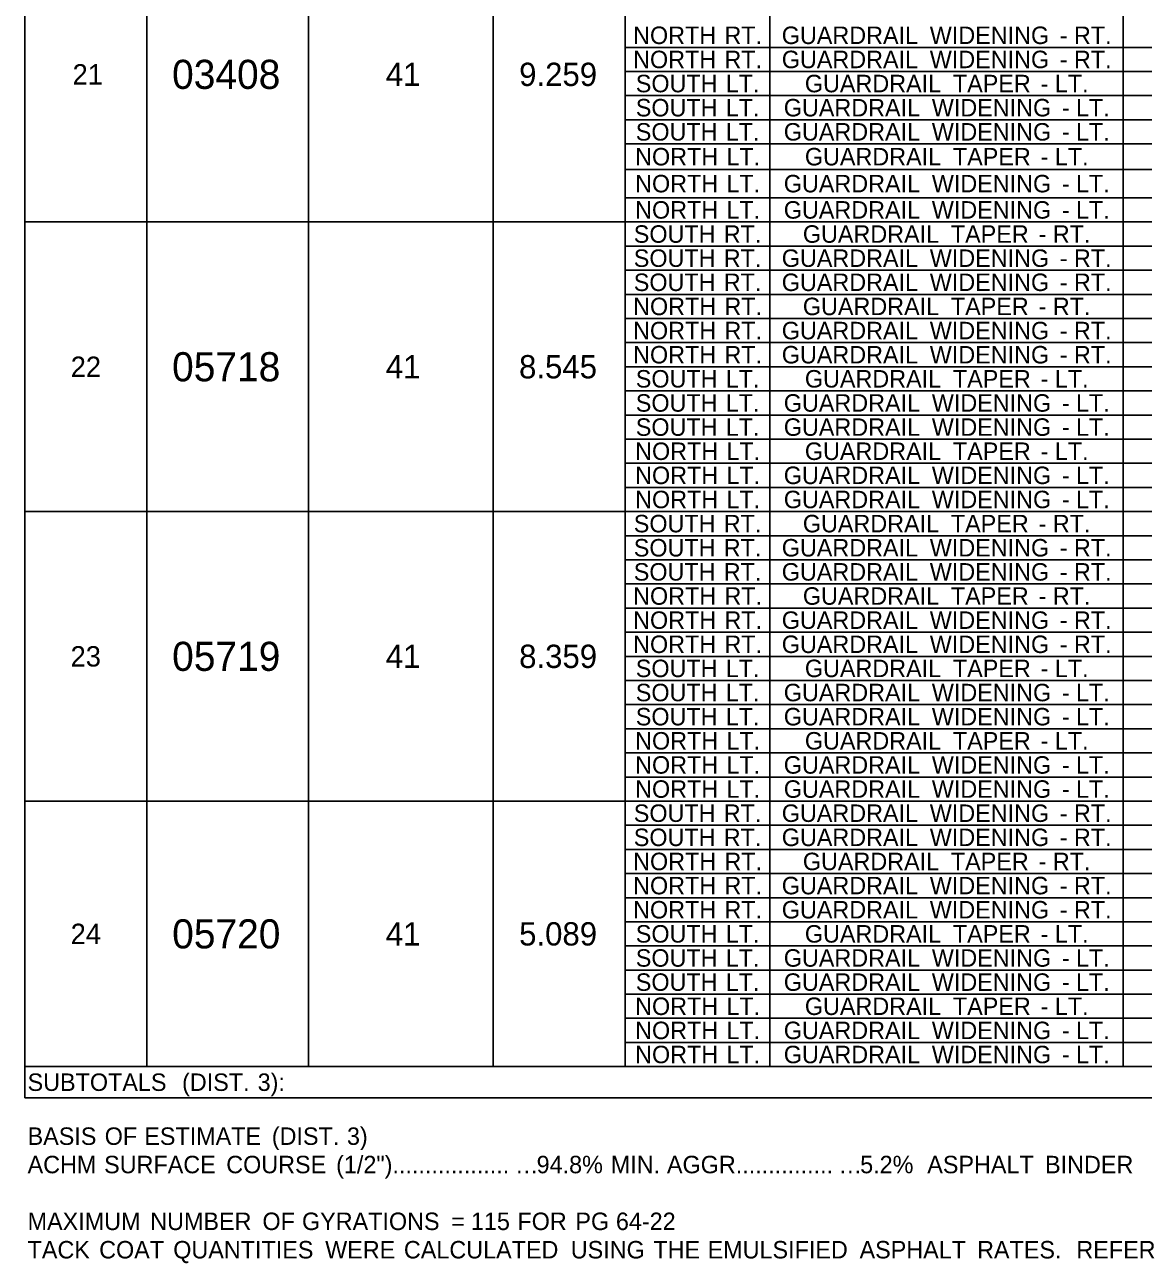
# Model space of a CAD drawing. Extents: x 544250 to 1930787, y -1948365 to 596640.
# Drawn here: x 557554.3 to 557938.5, y -1946895.1 to -1946469.8 of the extents above; entities that cross this region are included whole.
import ezdxf

# ---------------------------------------------------------------- set-up
doc = ezdxf.new("R2010")
doc.units = 0
doc.layers.add('Default', color=7, linetype='Continuous')

msp = doc.modelspace()

# ---------------------------------------------------------------- linework, layer by layer
at = {"layer": 'Default'}
for p, q in [((557554.29, -1946838.27), (557554.29, -1946062.17)), ((557596.21, -1946827.55), (557596.21, -1946062.17)), ((557651.79, -1946827.55), (557651.79, -1946062.17)), ((557715.16, -1946827.55), (557715.16, -1946062.17)), ((557760.5, -1946827.55), (557760.5, -1946062.17)), ((557810.22, -1946827.55), (557810.22, -1946062.17)), ((557931.61, -1946827.55), (557931.61, -1946062.17)), ((557760.5, -1946477.52), (558237.27, -1946477.52)), ((557760.5, -1946485.81), (558237.27, -1946485.81)), ((557760.5, -1946494.1), (558237.27, -1946494.1)), ((557760.5, -1946502.39), (558237.27, -1946502.39)), ((557760.5, -1946510.67), (558237.27, -1946510.67)), ((557760.5, -1946519.45), (558237.27, -1946519.45)), ((557760.5, -1946529.2), (558237.27, -1946529.2)), ((557554.29, -1946537.49), (558237.27, -1946537.49)), ((557760.5, -1946545.77), (558237.27, -1946545.77)), ((557760.5, -1946554.06), (558237.27, -1946554.06)), ((557760.5, -1946562.35), (558237.27, -1946562.35)), ((557760.5, -1946570.64), (558237.27, -1946570.64)), ((557760.5, -1946578.92), (558237.27, -1946578.92)), ((557760.5, -1946587.21), (558237.27, -1946587.21)), ((557760.5, -1946595.5), (558237.27, -1946595.5)), ((557760.5, -1946603.79), (558237.27, -1946603.79)), ((557760.5, -1946612.07), (558237.27, -1946612.07)), ((557760.5, -1946620.36), (558237.27, -1946620.36)), ((557760.5, -1946628.65), (558237.27, -1946628.65)), ((557554.29, -1946636.94), (558237.27, -1946636.94)), ((557760.5, -1946645.22), (558237.27, -1946645.22)), ((557760.5, -1946653.51), (558237.27, -1946653.51)), ((557760.5, -1946661.8), (558237.27, -1946661.8)), ((557760.5, -1946670.09), (558237.27, -1946670.09)), ((557760.5, -1946678.37), (558237.27, -1946678.37)), ((557760.5, -1946686.66), (558237.27, -1946686.66)), ((557760.5, -1946694.95), (558237.27, -1946694.95)), ((557760.5, -1946703.24), (558237.27, -1946703.24)), ((557760.5, -1946711.52), (558237.27, -1946711.52)), ((557760.5, -1946719.81), (558237.27, -1946719.81)), ((557760.5, -1946728.1), (558237.27, -1946728.1)), ((557554.29, -1946736.39), (558237.27, -1946736.39)), ((557760.5, -1946736.39), (558237.27, -1946736.39)), ((557760.5, -1946744.67), (558237.27, -1946744.67)), ((557760.5, -1946752.96), (558237.27, -1946752.96)), ((557760.5, -1946761.25), (558237.27, -1946761.25)), ((557760.5, -1946769.54), (558237.27, -1946769.54)), ((557760.5, -1946777.82), (558237.27, -1946777.82)), ((557760.5, -1946786.11), (558237.27, -1946786.11)), ((557760.5, -1946794.4), (558237.27, -1946794.4)), ((557760.5, -1946802.69), (558237.27, -1946802.69)), ((557760.5, -1946810.97), (558237.27, -1946810.97)), ((557760.5, -1946819.26), (558237.27, -1946819.26)), ((557554.29, -1946827.55), (558237.27, -1946827.55)), ((557554.29, -1946838.27), (558237.27, -1946838.27))]:
    msp.add_line(p, q, dxfattribs=at)

# ---------------------------------------------------------------- texts
for s, height, p in [('NORTH', 6, (557763.25, -1946476.38)), (' RT.', 6, (557792.38, -1946476.38)), ('GUARDRAIL', 6, (557814.31, -1946476.38)), (' WIDENING', 6, (557862.92, -1946476.38)), (' RT.', 6, (557912.43, -1946476.38)), (' -', 6, (557907.57, -1946476.38)), ('NORTH', 6, (557763.25, -1946484.67)), (' RT.', 6, (557792.38, -1946484.67)), ('GUARDRAIL', 6, (557814.31, -1946484.67)), (' WIDENING', 6, (557862.92, -1946484.67)), (' RT.', 6, (557912.43, -1946484.67)), ('21', 7, (557570.71, -1946490.29)), ('03408', 10, (557604.89, -1946491.79)), ('41', 8, (557678.29, -1946490.79)), ('9.259', 8, (557724.1, -1946490.79)), (' -', 6, (557907.57, -1946484.67)), ('SOUTH', 6, (557764.17, -1946492.95)), (' LT.', 6, (557792.84, -1946492.95)), ('GUARDRAIL', 6, (557822.24, -1946492.95)), (' TAPER', 6, (557870.86, -1946492.95)), (' LT.', 6, (557905.89, -1946492.95)), (' -', 6, (557901.03, -1946492.95)), ('SOUTH', 6, (557764.17, -1946501.24)), (' LT.', 6, (557792.84, -1946501.24)), ('GUARDRAIL', 6, (557815, -1946501.24)), (' WIDENING', 6, (557863.62, -1946501.24)), (' LT.', 6, (557913.13, -1946501.24)), (' -', 6, (557908.27, -1946501.24)), ('SOUTH', 6, (557764.17, -1946509.53)), (' LT.', 6, (557792.84, -1946509.53)), ('GUARDRAIL', 6, (557815, -1946509.53)), (' WIDENING', 6, (557863.62, -1946509.53)), (' LT.', 6, (557913.13, -1946509.53)), (' -', 6, (557908.27, -1946509.53)), ('NORTH', 6, (557763.94, -1946518.06)), (' LT.', 6, (557793.07, -1946518.06)), ('GUARDRAIL', 6, (557822.24, -1946518.06)), (' TAPER', 6, (557870.86, -1946518.06)), (' LT.', 6, (557905.89, -1946518.06)), (' -', 6, (557901.03, -1946518.06)), ('NORTH', 6, (557763.94, -1946527.32)), (' LT.', 6, (557793.07, -1946527.32)), ('GUARDRAIL', 6, (557815, -1946527.32)), (' WIDENING', 6, (557863.62, -1946527.32)), (' LT.', 6, (557913.13, -1946527.32)), (' -', 6, (557908.27, -1946527.32)), ('NORTH', 6, (557763.94, -1946536.34)), (' LT.', 6, (557793.07, -1946536.34)), ('GUARDRAIL', 6, (557815, -1946536.34)), (' WIDENING', 6, (557863.62, -1946536.34)), (' LT.', 6, (557913.13, -1946536.34)), (' -', 6, (557908.27, -1946536.34)), ('SOUTH', 6, (557763.48, -1946544.63)), (' RT.', 6, (557792.15, -1946544.63)), ('GUARDRAIL', 6, (557821.55, -1946544.63)), (' TAPER', 6, (557870.16, -1946544.63)), (' RT.', 6, (557905.19, -1946544.63)), (' -', 6, (557900.33, -1946544.63)), ('SOUTH', 6, (557763.48, -1946552.92)), (' RT.', 6, (557792.15, -1946552.92)), ('GUARDRAIL', 6, (557814.31, -1946552.92)), (' WIDENING', 6, (557862.92, -1946552.92)), (' RT.', 6, (557912.43, -1946552.92)), (' -', 6, (557907.57, -1946552.92)), ('SOUTH', 6, (557763.48, -1946561.2)), (' RT.', 6, (557792.15, -1946561.2)), ('GUARDRAIL', 6, (557814.31, -1946561.2)), (' WIDENING', 6, (557862.92, -1946561.2)), (' RT.', 6, (557912.43, -1946561.2)), (' -', 6, (557907.57, -1946561.2)), ('NORTH', 6, (557763.25, -1946569.49)), (' RT.', 6, (557792.38, -1946569.49)), ('GUARDRAIL', 6, (557821.55, -1946569.49)), (' TAPER', 6, (557870.16, -1946569.49)), (' RT.', 6, (557905.19, -1946569.49)), (' -', 6, (557900.33, -1946569.49)), ('NORTH', 6, (557763.25, -1946577.78)), (' RT.', 6, (557792.38, -1946577.78)), ('GUARDRAIL', 6, (557814.31, -1946577.78)), (' WIDENING', 6, (557862.92, -1946577.78)), (' RT.', 6, (557912.43, -1946577.78)), (' -', 6, (557907.57, -1946577.78)), ('05718', 10, (557604.89, -1946592.21)), ('NORTH', 6, (557763.25, -1946586.07)), (' RT.', 6, (557792.38, -1946586.07)), ('GUARDRAIL', 6, (557814.31, -1946586.07)), (' WIDENING', 6, (557862.92, -1946586.07)), (' RT.', 6, (557912.43, -1946586.07)), ('22', 7, (557570.07, -1946590.71)), ('41', 8, (557678.29, -1946591.21)), ('8.545', 8, (557724.07, -1946591.21)), (' -', 6, (557907.57, -1946586.07)), ('SOUTH', 6, (557764.17, -1946594.35)), (' LT.', 6, (557792.84, -1946594.35)), ('GUARDRAIL', 6, (557822.24, -1946594.35)), (' TAPER', 6, (557870.86, -1946594.35)), (' LT.', 6, (557905.89, -1946594.35)), (' -', 6, (557901.03, -1946594.35)), ('SOUTH', 6, (557764.17, -1946602.64)), (' LT.', 6, (557792.84, -1946602.64)), ('GUARDRAIL', 6, (557815, -1946602.64)), (' WIDENING', 6, (557863.62, -1946602.64)), (' LT.', 6, (557913.13, -1946602.64)), (' -', 6, (557908.27, -1946602.64)), ('SOUTH', 6, (557764.17, -1946610.93)), (' LT.', 6, (557792.84, -1946610.93)), ('GUARDRAIL', 6, (557815, -1946610.93)), (' WIDENING', 6, (557863.62, -1946610.93)), (' -', 6, (557908.27, -1946610.93)), (' LT.', 6, (557913.13, -1946610.93)), ('NORTH', 6, (557763.94, -1946619.22)), (' LT.', 6, (557793.07, -1946619.22)), ('GUARDRAIL', 6, (557822.24, -1946619.22)), (' TAPER', 6, (557870.86, -1946619.22)), (' -', 6, (557901.03, -1946619.22)), (' LT.', 6, (557905.89, -1946619.22)), ('NORTH', 6, (557763.94, -1946627.5)), (' LT.', 6, (557793.07, -1946627.5)), ('GUARDRAIL', 6, (557815, -1946627.5)), (' WIDENING', 6, (557863.62, -1946627.5)), (' -', 6, (557908.27, -1946627.5)), (' LT.', 6, (557913.13, -1946627.5)), ('NORTH', 6, (557763.94, -1946635.79)), (' LT.', 6, (557793.07, -1946635.79)), ('GUARDRAIL', 6, (557815, -1946635.79)), (' WIDENING', 6, (557863.62, -1946635.79)), (' -', 6, (557908.27, -1946635.79)), (' LT.', 6, (557913.13, -1946635.79)), ('SOUTH', 6, (557763.48, -1946644.08)), ('GUARDRAIL', 6, (557821.55, -1946644.08)), (' RT.', 6, (557792.15, -1946644.08)), (' TAPER', 6, (557870.16, -1946644.08)), (' -', 6, (557900.33, -1946644.08)), (' RT.', 6, (557905.19, -1946644.08)), ('SOUTH', 6, (557763.48, -1946652.37)), (' RT.', 6, (557792.15, -1946652.37)), ('GUARDRAIL', 6, (557814.31, -1946652.37)), (' WIDENING', 6, (557862.92, -1946652.37)), (' RT.', 6, (557912.43, -1946652.37)), (' -', 6, (557907.57, -1946652.37)), ('SOUTH', 6, (557763.48, -1946660.65)), (' RT.', 6, (557792.15, -1946660.65)), ('GUARDRAIL', 6, (557814.31, -1946660.65)), (' WIDENING', 6, (557862.92, -1946660.65)), (' RT.', 6, (557912.43, -1946660.65)), (' -', 6, (557907.57, -1946660.65)), ('NORTH', 6, (557763.25, -1946668.94)), (' RT.', 6, (557792.38, -1946668.94)), ('GUARDRAIL', 6, (557821.55, -1946668.94)), (' TAPER', 6, (557870.16, -1946668.94)), (' RT.', 6, (557905.19, -1946668.94)), (' -', 6, (557900.33, -1946668.94)), ('NORTH', 6, (557763.25, -1946677.23)), (' RT.', 6, (557792.38, -1946677.23)), ('GUARDRAIL', 6, (557814.31, -1946677.23)), (' WIDENING', 6, (557862.92, -1946677.23)), (' RT.', 6, (557912.43, -1946677.23)), (' -', 6, (557907.57, -1946677.23)), ('NORTH', 6, (557763.25, -1946685.52)), (' RT.', 6, (557792.38, -1946685.52)), ('GUARDRAIL', 6, (557814.31, -1946685.52)), (' WIDENING', 6, (557862.92, -1946685.52)), (' RT.', 6, (557912.43, -1946685.52)), ('23', 7, (557570.03, -1946690.16)), ('05719', 10, (557604.91, -1946691.66)), ('41', 8, (557678.29, -1946690.66)), ('8.359', 8, (557724.1, -1946690.66)), (' -', 6, (557907.57, -1946685.52)), ('SOUTH', 6, (557764.17, -1946693.8)), (' LT.', 6, (557792.84, -1946693.8)), ('GUARDRAIL', 6, (557822.24, -1946693.8)), (' TAPER', 6, (557870.86, -1946693.8)), (' LT.', 6, (557905.89, -1946693.8)), (' -', 6, (557901.03, -1946693.8)), ('SOUTH', 6, (557764.17, -1946702.09)), (' LT.', 6, (557792.84, -1946702.09)), ('GUARDRAIL', 6, (557815, -1946702.09)), (' WIDENING', 6, (557863.62, -1946702.09)), (' LT.', 6, (557913.13, -1946702.09)), (' -', 6, (557908.27, -1946702.09)), ('SOUTH', 6, (557764.17, -1946710.38)), (' LT.', 6, (557792.84, -1946710.38)), ('GUARDRAIL', 6, (557815, -1946710.38)), (' WIDENING', 6, (557863.62, -1946710.38)), (' LT.', 6, (557913.13, -1946710.38)), (' -', 6, (557908.27, -1946710.38)), ('NORTH', 6, (557763.94, -1946718.67)), (' LT.', 6, (557793.07, -1946718.67)), ('GUARDRAIL', 6, (557822.24, -1946718.67)), (' TAPER', 6, (557870.86, -1946718.67)), (' LT.', 6, (557905.89, -1946718.67)), (' -', 6, (557901.03, -1946718.67)), ('NORTH', 6, (557763.94, -1946726.95)), (' LT.', 6, (557793.07, -1946726.95)), ('GUARDRAIL', 6, (557815, -1946726.95)), (' WIDENING', 6, (557863.62, -1946726.95)), (' LT.', 6, (557913.13, -1946726.95)), (' -', 6, (557908.27, -1946726.95)), ('NORTH', 6, (557763.94, -1946735.24)), (' LT.', 6, (557793.07, -1946735.24)), ('GUARDRAIL', 6, (557815, -1946735.24)), (' WIDENING', 6, (557863.62, -1946735.24)), (' LT.', 6, (557913.13, -1946735.24)), (' -', 6, (557908.27, -1946735.24)), ('SOUTH', 6, (557763.48, -1946743.53)), (' RT.', 6, (557792.15, -1946743.53)), ('GUARDRAIL', 6, (557814.31, -1946743.53)), (' WIDENING', 6, (557862.92, -1946743.53)), (' RT.', 6, (557912.43, -1946743.53)), (' -', 6, (557907.57, -1946743.53)), ('SOUTH', 6, (557763.48, -1946751.82)), (' RT.', 6, (557792.15, -1946751.82)), ('GUARDRAIL', 6, (557814.31, -1946751.82)), (' WIDENING', 6, (557862.92, -1946751.82)), (' RT.', 6, (557912.43, -1946751.82)), (' -', 6, (557907.57, -1946751.82)), ('NORTH', 6, (557763.25, -1946760.1)), (' RT.', 6, (557792.38, -1946760.1)), ('GUARDRAIL', 6, (557821.55, -1946760.1)), (' TAPER', 6, (557870.16, -1946760.1)), (' RT.', 6, (557905.19, -1946760.1)), (' -', 6, (557900.33, -1946760.1)), ('NORTH', 6, (557763.25, -1946768.39)), (' RT.', 6, (557792.38, -1946768.39)), ('GUARDRAIL', 6, (557814.31, -1946768.39)), (' WIDENING', 6, (557862.92, -1946768.39)), (' RT.', 6, (557912.43, -1946768.39)), (' -', 6, (557907.57, -1946768.39)), ('NORTH', 6, (557763.25, -1946776.68)), (' RT.', 6, (557792.38, -1946776.68)), ('GUARDRAIL', 6, (557814.31, -1946776.68)), (' WIDENING', 6, (557862.92, -1946776.68)), (' -', 6, (557907.57, -1946776.68)), (' RT.', 6, (557912.43, -1946776.68)), ('24', 7, (557570.05, -1946785.47)), ('05720', 10, (557604.92, -1946786.97)), ('41', 8, (557678.29, -1946785.97)), ('5.089', 8, (557724.1, -1946785.97)), ('SOUTH', 6, (557764.17, -1946784.97)), (' LT.', 6, (557792.84, -1946784.97)), ('GUARDRAIL', 6, (557822.24, -1946784.97)), (' TAPER', 6, (557870.86, -1946784.97)), (' -', 6, (557901.03, -1946784.97)), (' LT.', 6, (557905.89, -1946784.97)), ('SOUTH', 6, (557764.17, -1946793.25)), (' LT.', 6, (557792.84, -1946793.25)), ('GUARDRAIL', 6, (557815, -1946793.25)), (' WIDENING', 6, (557863.62, -1946793.25)), (' -', 6, (557908.27, -1946793.25)), (' LT.', 6, (557913.13, -1946793.25)), ('SOUTH', 6, (557764.17, -1946801.54)), (' LT.', 6, (557792.84, -1946801.54)), ('GUARDRAIL', 6, (557815, -1946801.54)), (' WIDENING', 6, (557863.62, -1946801.54)), (' -', 6, (557908.27, -1946801.54)), (' LT.', 6, (557913.13, -1946801.54)), ('NORTH', 6, (557763.94, -1946809.83)), (' LT.', 6, (557793.07, -1946809.83)), ('GUARDRAIL', 6, (557822.24, -1946809.83)), (' TAPER', 6, (557870.86, -1946809.83)), (' LT.', 6, (557905.89, -1946809.83)), (' -', 6, (557901.03, -1946809.83)), ('NORTH', 6, (557763.94, -1946818.12)), (' LT.', 6, (557793.07, -1946818.12)), ('GUARDRAIL', 6, (557815, -1946818.12)), (' WIDENING', 6, (557863.62, -1946818.12)), (' LT.', 6, (557913.13, -1946818.12)), (' -', 6, (557908.27, -1946818.12)), ('NORTH', 6, (557763.94, -1946826.4)), (' LT.', 6, (557793.07, -1946826.4)), ('GUARDRAIL', 6, (557815, -1946826.4)), (' WIDENING', 6, (557863.62, -1946826.4)), (' LT.', 6, (557913.13, -1946826.4)), (' -', 6, (557908.27, -1946826.4)), ('SUBTOTALS', 6, (557555.26, -1946835.91)), (' (DIST.', 6, (557606.09, -1946835.91)), (' 3):', 6, (557632.05, -1946835.91)), ('BASIS', 6, (557555.26, -1946854.44)), (' OF', 6, (557579.52, -1946854.44)), (' ESTIMATE', 6, (557593.11, -1946854.44)), (' (DIST.', 6, (557636.92, -1946854.44)), (' 3)', 6, (557662.73, -1946854.44)), ('ACHM', 6, (557555.26, -1946864.19)), (' SURFACE', 6, (557579.32, -1946864.19)), (' COURSE', 6, (557621.26, -1946864.19)), (' (1/2")..................', 6, (557659.01, -1946864.19)), ('94.8%', 6, (557730.11, -1946864.19)), (' MIN.', 6, (557753.35, -1946864.19)), (' AGGR...............', 6, (557772.64, -1946864.19)), ('5.2%', 6, (557841.24, -1946864.19)), ('  ASPHALT', 6, (557859.83, -1946864.19)), (' BINDER', 6, (557902.52, -1946864.19)), ('…', 6, (557722.71, -1946864.19)), ('…', 6, (557833.85, -1946864.19)), ('MAXIMUM', 6, (557555.26, -1946883.69)), (' NUMBER', 6, (557595.15, -1946883.69)), (' OF', 6, (557633.7, -1946883.69)), (' GYRATIONS', 6, (557647.28, -1946883.69)), (' =', 6, (557698.55, -1946883.69)), (' 115', 6, (557705.31, -1946883.69)), (' FOR', 6, (557721.28, -1946883.69)), (' PG', 6, (557741.19, -1946883.69)), (' 64-22', 6, (557755.11, -1946883.69)), ('TACK', 6, (557555.26, -1946893.44)), (' COAT', 6, (557577.61, -1946893.44)), (' QUANTITIES', 6, (557603.06, -1946893.44)), (' WERE', 6, (557655.25, -1946893.44)), (' CALCULATED', 6, (557682.29, -1946893.44)), (' USING', 6, (557739.61, -1946893.44)), (' THE', 6, (557767.96, -1946893.44)), (' EMULSIFIED', 6, (557786.61, -1946893.44)), (' ASPHALT', 6, (557838.8, -1946893.44)), (' RATES.', 6, (557879.17, -1946893.44)), ('  REFER', 6, (557911.04, -1946893.44))]:
    msp.add_text(s, height=height, dxfattribs=at).set_placement(p)

doc.saveas('drawing.dxf')
